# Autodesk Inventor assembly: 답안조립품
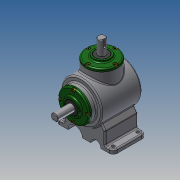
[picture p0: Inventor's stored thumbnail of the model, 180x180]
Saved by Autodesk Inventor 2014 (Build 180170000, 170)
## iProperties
Created: 2018-08
Part Number: 답안조립품
Document SubType Name: Assembly
Designer: kb542
Author: kb542
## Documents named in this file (14)
- C:\Users\kb542\Desktop\480807V1020\답안조립품.iam
- C:\Users\kb542\Desktop\480807V1020\본체.ipt
- C:\Users\kb542\Desktop\480807V1020\메인 축.ipt
- 메인 축.ipt
- C:\Users\kb542\Desktop\480807V1020\베어링 6203.ipt
- C:\Users\kb542\Desktop\480807V1020\오일실 17 32 8.ipt
- C:\Users\kb542\Desktop\480807V1020\커버.ipt
- C:\Users\kb542\Desktop\480807V1020\키 5x5.ipt
- C:\Users\kb542\Desktop\480807V1020\메인 베벨기어.ipt
- C:\Users\kb542\Desktop\480807V1020\서브 베벨기어.ipt
- C:\Users\kb542\Desktop\480807V1020\서브 축.ipt
- 서브 축.ipt
- C:\Users\kb542\Desktop\480807V1020\키 4x4.ipt
- C:\Users\kb542\Desktop\480807V1020\볼트 M4.ipt
